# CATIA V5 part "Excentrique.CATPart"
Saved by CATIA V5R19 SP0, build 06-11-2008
Part number: Excentrique
Bounding box of the stored display mesh (mm): x -15 to 15, y 0 to 300, z -10 to 20
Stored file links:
  E:\IAO_2010\iao\IAO_MMS_Groupe2\IAO_MMS_Groupe2\svallart\Assemblage\Excentrique.CATPart
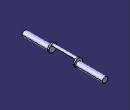
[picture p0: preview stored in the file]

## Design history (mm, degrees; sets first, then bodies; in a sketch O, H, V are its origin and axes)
Body1 (main body)
  Sketch1 on zx-plane, origin (0, 0, 0), H (-1, 0, 0), V (0, 0, 1)
    circle A1 centre (0, 0) radius 10
    radius A1 = 10
  Pad1: profile Sketch1, direction (0, 1, 0), length 100
  Sketch2 on end face of Pad1, origin (0, 100, 0), H (-1, 0, 0), V (0, 0, 1)
    circle A1 centre (0, 5) radius 15
    point P1 (0, 5)
    point P2 (0, -10)
    reference projected circle E1 centre (0, 0) radius 10 from edge [face of Pad1 from Sketch1.A1 | end face of Pad1]
    radius A1 = 15
    coincidence: P1 V, A1 P2, P2 V
    tangency: E1 A1
  Pad2: profile Sketch2, direction (0, 1, 0), length 5
  Sketch3 on end face of Pad2, origin (0, 105, 0), H (-1, 0, 0), V (0, 0, 1)
    circle A1 centre (0, 15) radius 5
    point P1 (0, 15)
    point P2 (0, 20)
    reference projected circle E1 centre (0, 5) radius 15 from edge [face of Pad2 from Sketch2.A1 | end face of Pad2]
    radius A1 = 5
    coincidence: A1 P2, P2 V, P1 V
    tangency: E1 A1
  Pad3: profile Sketch3, direction (0, 1, 0), length 45
  Plane1: type Offset, RefPlane end face of Pad3, Offset 0, reversed
  Mirror1: of the body so far, about Plane1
